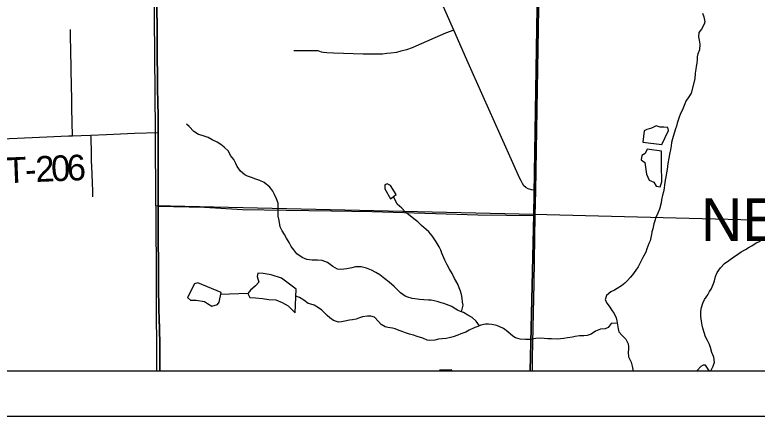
# Model space of a CAD drawing. Extents: x 0 to 34, y -5 to 22.
# Drawn here: x 5.836 to 7.476, y 14 to 14.888 of the extents above; entities that cross this region are included whole.
import ezdxf

# ---------------------------------------------------------------- set-up
doc = ezdxf.new("R2010")
doc.units = 0
for name, color, linetype in [('GM_X_City_Street', 7, 'Continuous'), ('GM_X_Corporation_Text', 7, 'Continuous'), ('GM_X_County_Road', 7, 'Continuous'), ('GM_X_Minor_Lake', 7, 'Continuous'), ('GM_X_Minor_River', 7, 'Continuous'), ('GM_X_Section', 7, 'Continuous'), ('GM_X_Township_Road', 7, 'Continuous'), ('GM_X_Township_Road_Text', 7, 'Continuous'), ('GM_X_US_Route', 7, 'Continuous'), ('SC_Scratch2', 7, 'Continuous'), ('SH_Cut_Line', 7, 'Continuous'), ('SH_Data', 7, 'Continuous')]:
    doc.layers.add(name, color=color, linetype=linetype)

msp = doc.modelspace()

# ---------------------------------------------------------------- linework, layer by layer
at = {"layer": 'GM_X_City_Street'}
for points in [[(6.1486, 14.1), (6.9745, 14.1), (6.9822, 14.4457), (6.1471, 14.4654)], [(6.9745, 14.1), (8.0304, 14.1), (8.041, 14.419), (6.9822, 14.4457)]]:
    msp.add_lwpolyline(points, close=True, dxfattribs=at)
at = {"layer": 'GM_X_County_Road'}
for points in [[(6.987, 14.4985), (6.9943, 14.9477), (7.0004, 15.2464)], [(6.987, 14.4985), (6.9828, 14.4997), (6.9775, 14.5009), (6.9703, 14.5028), (6.9652, 14.5054), (6.9603, 14.5095), (6.9573, 14.5146), (6.9542, 14.5205), (6.9516, 14.5258), (6.9082, 14.623), (6.8707, 14.7073), (6.8348, 14.7884), (6.8057, 14.8538), (6.7632, 14.9507)], [(6.9794, 14.1), (6.9799, 14.1287), (6.9832, 14.2943), (6.9858, 14.4439), (6.987, 14.4985)]]:
    msp.add_lwpolyline(points, dxfattribs=at)
at = {"layer": 'GM_X_Minor_Lake'}
msp.add_line((6.8012, 14.1), (6.8003, 14.1023), dxfattribs=at)
for points in [[(7.2658, 14.6009), (7.2803, 14.6314), (7.2787, 14.6386), (7.2696, 14.6389), (7.2617, 14.6389), (7.2529, 14.6418), (7.2427, 14.6368), (7.2325, 14.634), (7.2261, 14.6313), (7.2233, 14.6058)], [(7.2233, 14.6058), (7.2658, 14.6009)], [(7.2329, 14.5907), (7.2288, 14.5812), (7.2216, 14.5766), (7.2194, 14.5671), (7.2278, 14.5607), (7.2315, 14.5349), (7.2373, 14.522), (7.2476, 14.5175), (7.2526, 14.5085), (7.2621, 14.507), (7.2657, 14.5181), (7.2647, 14.5553), (7.2648, 14.5857)], [(7.2648, 14.5857), (7.2329, 14.5907)], [(6.6783, 14.4902), (6.6656, 14.5102), (6.6584, 14.514), (6.6531, 14.5113), (6.6535, 14.5029), (6.6659, 14.4806)], [(6.6659, 14.4806), (6.6783, 14.4902)], [(6.4572, 14.2805), (6.4247, 14.3053), (6.4019, 14.3127), (6.3841, 14.3152), (6.3727, 14.3162), (6.3709, 14.3086), (6.3751, 14.2965), (6.3676, 14.2881), (6.3567, 14.2789), (6.3503, 14.2716), (6.355, 14.2625), (6.3671, 14.2615), (6.3827, 14.2605), (6.3967, 14.2583), (6.4123, 14.2573), (6.4263, 14.2514), (6.4393, 14.2443), (6.455, 14.2284)], [(6.2398, 14.2946), (6.2326, 14.293), (6.2169, 14.2621), (6.2234, 14.2568), (6.2363, 14.2569), (6.2549, 14.2537), (6.2614, 14.2488), (6.2706, 14.2432), (6.2834, 14.2471), (6.2868, 14.2524), (6.2912, 14.2734)], [(6.2912, 14.2734), (6.2398, 14.2946)], [(6.455, 14.2284), (6.4572, 14.2805)], [(7.3707, 14.1), (7.3701, 14.1006), (7.3647, 14.1082), (7.362, 14.1131), (7.3567, 14.1127), (7.3518, 14.1099), (7.3428, 14.1)], [(6.8003, 14.1023), (6.7742, 14.1017), (6.7746, 14.1)]]:
    msp.add_lwpolyline(points, dxfattribs=at)
at = {"layer": 'GM_X_Minor_River'}
for points in [[(7.3552, 14.8912), (7.3579, 14.8833), (7.3603, 14.8723)], [(7.3603, 14.8723), (7.3592, 14.8666), (7.3532, 14.8559), (7.3469, 14.8486), (7.3466, 14.8391), (7.3478, 14.8319), (7.3494, 14.8228), (7.3484, 14.8102), (7.345, 14.8015), (7.3436, 14.795), (7.3433, 14.7893), (7.3426, 14.7809), (7.3411, 14.7733), (7.3404, 14.7676), (7.339, 14.7585), (7.3384, 14.7459), (7.3304, 14.7143)], [(7.3304, 14.7143), (7.3248, 14.7063), (7.3188, 14.6967), (7.3162, 14.691), (7.3117, 14.6799), (7.3058, 14.6673), (7.3036, 14.6609), (7.2995, 14.6479), (7.2977, 14.6414), (7.2954, 14.6357), (7.2929, 14.6258), (7.2892, 14.6136), (7.287, 14.6053), (7.2859, 14.598), (7.2845, 14.5893), (7.283, 14.5832), (7.2808, 14.5706), (7.2787, 14.5585), (7.2776, 14.552), (7.2769, 14.5455), (7.2758, 14.5383), (7.2744, 14.5284), (7.2729, 14.5216), (7.2711, 14.5113), (7.2704, 14.5041), (7.269, 14.4961), (7.2671, 14.4885), (7.265, 14.4782), (7.2639, 14.4721), (7.2606, 14.458), (7.2569, 14.4492), (7.2524, 14.4397), (7.2498, 14.4317), (7.248, 14.4252), (7.2458, 14.4146), (7.2436, 14.4073), (7.2429, 14.4016), (7.241, 14.3948), (7.2396, 14.3879), (7.237, 14.3815), (7.2325, 14.37), (7.2299, 14.3624), (7.2236, 14.3506), (7.2191, 14.3418), (7.2132, 14.33), (7.2083, 14.3227), (7.2008, 14.3124), (7.1955, 14.3063), (7.1899, 14.3001), (7.1835, 14.294), (7.176, 14.2879), (7.1666, 14.2825), (7.1605, 14.2786), (7.1526, 14.2747), (7.1432, 14.2671), (7.1399, 14.2575), (7.1449, 14.2488), (7.1506, 14.2409), (7.1556, 14.233), (7.1598, 14.2269), (7.1645, 14.2171), (7.1657, 14.211), (7.1673, 14.2019), (7.1689, 14.1932), (7.1704, 14.1864), (7.1777, 14.1785), (7.1857, 14.1702), (7.1908, 14.16), (7.1916, 14.1543), (7.1916, 14.1482), (7.1913, 14.1414), (7.1918, 14.1315), (7.1976, 14.1194), (7.1999, 14.1103), (7.2011, 14.1035), (7.2013, 14.1)], [(6.8625, 14.2), (6.8551, 14.2099), (6.8463, 14.2182), (6.8368, 14.2234), (6.8269, 14.229), (6.8201, 14.2316), (6.814, 14.2346), (6.8067, 14.2387), (6.801, 14.2428), (6.7839, 14.2495), (6.7778, 14.251), (6.7687, 14.2539), (6.7619, 14.2554), (6.7554, 14.2565), (6.7497, 14.2568), (6.7395, 14.2575), (6.73, 14.2582), (6.7194, 14.2592), (6.7137, 14.2603), (6.7042, 14.2629), (6.6981, 14.2651), (6.6881, 14.273), (6.6813, 14.2794), (6.6736, 14.2866), (6.6625, 14.2963), (6.6534, 14.3039), (6.6423, 14.3125), (6.6335, 14.3177), (6.6236, 14.323), (6.6126, 14.3274), (6.6008, 14.3304), (6.5883, 14.3299), (6.5804, 14.3279), (6.5694, 14.3259), (6.5629, 14.3251), (6.5546, 14.3247), (6.5485, 14.3254), (6.5383, 14.331), (6.5268, 14.34), (6.515, 14.3444), (6.5044, 14.3451), (6.4923, 14.345), (6.4812, 14.3464), (6.4702, 14.3509), (6.4591, 14.3592), (6.4522, 14.3675), (6.4461, 14.3754), (6.4415, 14.3837), (6.4361, 14.3935), (6.4315, 14.4018), (6.4265, 14.4102), (6.4222, 14.4189), (6.4195, 14.4325), (6.4178, 14.442), (6.4174, 14.4507), (6.4173, 14.4568), (6.4177, 14.4648), (6.4172, 14.4712), (6.4141, 14.4803), (6.4095, 14.4905), (6.4056, 14.4974), (6.3991, 14.5064), (6.3869, 14.5169), (6.377, 14.521), (6.3682, 14.5244), (6.3587, 14.5277), (6.35, 14.5311), (6.3439, 14.5337), (6.3339, 14.5419), (6.3267, 14.5521), (6.3239, 14.5589), (6.3193, 14.5673), (6.312, 14.5763), (6.3074, 14.5858), (6.2982, 14.5952), (6.291, 14.6008), (6.2826, 14.6057), (6.2719, 14.6113), (6.2628, 14.6162), (6.2563, 14.6188), (6.2498, 14.6206), (6.2415, 14.6232), (6.2312, 14.6299), (6.2209, 14.6409), (6.2147, 14.6454)], [(6.8226, 14.2306), (6.8264, 14.2457), (6.8252, 14.2522), (6.824, 14.2609), (6.8228, 14.2689), (6.8204, 14.2764), (6.8177, 14.2836), (6.8146, 14.2916), (6.8069, 14.3048), (6.8023, 14.3158), (6.7958, 14.3248), (6.7907, 14.3347), (6.7857, 14.3453), (6.7795, 14.3604), (6.7772, 14.3668), (6.773, 14.3748), (6.7668, 14.3858), (6.758, 14.3986), (6.7507, 14.4076), (6.7449, 14.4125), (6.7346, 14.4219), (6.7262, 14.4298), (6.7201, 14.434), (6.706, 14.4452), (6.6991, 14.4513), (6.6911, 14.4599), (6.6804, 14.469), (6.6721, 14.4855)], [(7.3736, 14.1), (7.3791, 14.1103), (7.382, 14.1191), (7.3804, 14.1305), (7.3757, 14.141), (7.373, 14.1517), (7.3706, 14.1585), (7.366, 14.1672), (7.3621, 14.1755), (7.3562, 14.1944), (7.3543, 14.2016), (7.353, 14.2103), (7.3514, 14.2206), (7.3513, 14.232), (7.3528, 14.2403), (7.3561, 14.2499), (7.3594, 14.2579), (7.3673, 14.2682), (7.3706, 14.2755), (7.3747, 14.2812), (7.3792, 14.2915), (7.3818, 14.2992), (7.3843, 14.3087), (7.3877, 14.3178), (7.3952, 14.3278), (7.4042, 14.3374), (7.4132, 14.3443), (7.4242, 14.352), (7.4302, 14.3563), (7.4407, 14.3632), (7.4502, 14.3683), (7.4585, 14.3737), (7.4645, 14.3768), (7.4736, 14.383), (7.4834, 14.3869)], [(6.3503, 14.2716), (6.2903, 14.2693)], [(7.1666, 14.2059), (7.1536, 14.2052), (7.1465, 14.1964), (7.14, 14.1933), (7.1298, 14.1921), (7.1189, 14.1878), (7.1094, 14.1817), (7.1004, 14.1786), (7.0928, 14.1777), (7.0837, 14.1773), (7.0742, 14.1761), (7.0682, 14.1749), (7.0572, 14.1729), (7.0485, 14.1717), (7.0416, 14.1708), (7.0348, 14.1704), (7.0216, 14.1707), (7.0132, 14.171), (7.0052, 14.172), (6.9969, 14.1723), (6.987, 14.1719), (6.9742, 14.1699), (6.9643, 14.1694), (6.9522, 14.1704), (6.9423, 14.173), (6.9362, 14.1768), (6.9251, 14.1862), (6.9156, 14.1941), (6.9011, 14.2004), (6.8897, 14.203), (6.8821, 14.2036), (6.8757, 14.2036), (6.8651, 14.2012), (6.8587, 14.1981), (6.8522, 14.1958), (6.8398, 14.19), (6.8322, 14.1861), (6.8213, 14.1818), (6.8148, 14.1791), (6.8039, 14.1756), (6.7956, 14.1733), (6.7887, 14.1721), (6.78, 14.1712), (6.7721, 14.17), (6.7634, 14.1684), (6.7528, 14.1672), (6.7467, 14.1683), (6.7372, 14.1728), (6.7246, 14.1761), (6.7163, 14.179), (6.7075, 14.1816), (6.6991, 14.1846), (6.6919, 14.1872), (6.6851, 14.1898), (6.6759, 14.1931), (6.6702, 14.1946), (6.6596, 14.1964), (6.6539, 14.1979), (6.6455, 14.2024), (6.639, 14.2095), (6.6302, 14.2186), (6.6222, 14.2208), (6.6147, 14.2215), (6.6041, 14.2195), (6.5973, 14.2171), (6.5901, 14.2148), (6.5817, 14.2132), (6.5749, 14.212), (6.5647, 14.21), (6.5571, 14.2088), (6.5507, 14.208), (6.54, 14.2117), (6.5317, 14.2177), (6.5259, 14.2226), (6.5141, 14.2343), (6.5064, 14.2399), (6.4969, 14.2455), (6.4897, 14.2474), (6.484, 14.2492), (6.4744, 14.2567), (6.4649, 14.2623), (6.4565, 14.2651)]]:
    msp.add_lwpolyline(points, dxfattribs=at)
at = {"layer": 'GM_X_Section'}
for points in [[(6.139, 15.4711), (6.9989, 15.4538), (6.9822, 14.4457), (6.1471, 14.4654), (6.1461, 14.6292)], [(8.0646, 15.4287), (8.041, 14.419), (6.9822, 14.4457), (6.9989, 15.4538)]]:
    msp.add_lwpolyline(points, close=True, dxfattribs=at)
at = {"layer": 'GM_X_Township_Road'}
msp.add_line((6.1526, 14.6274), (6.1525, 14.6385), dxfattribs=at)
for points in [[(6.1525, 14.6385), (6.1523, 14.6635), (6.1517, 14.6944), (6.1513, 14.7224), (6.1509, 14.744), (6.1508, 14.7565), (6.1504, 14.7906), (6.1503, 14.8098), (6.1502, 14.859), (6.1488, 14.9428), (6.1486, 14.9707), (6.1469, 15.0732), (6.1462, 15.1478), (6.1454, 15.1975), (6.1445, 15.2627), (6.1441, 15.2967), (6.1441, 15.2993), (6.1441, 15.3023), (6.1441, 15.3068)], [(5.9628, 14.6201), (5.9616, 14.6802), (5.9613, 14.6999), (5.9607, 14.7331), (5.9601, 14.7642), (5.9592, 14.8139), (5.9587, 14.8343), (5.9586, 14.8374), (5.9586, 14.8418), (5.9586, 14.8469), (5.9588, 14.8554)], [(6.8057, 14.8538), (6.7876, 14.8467), (6.722, 14.818), (6.7134, 14.8145), (6.701, 14.8104), (6.6885, 14.807), (6.6788, 14.8045), (6.6667, 14.8027), (6.6574, 14.8017), (6.6478, 14.8009), (6.6358, 14.8005), (6.605, 14.8008), (6.5396, 14.8029), (6.5251, 14.8035), (6.518, 14.8041), (6.5131, 14.8053), (6.5062, 14.8078), (6.4518, 14.8076)], [(5.807, 14.6136), (5.8237, 14.6143), (5.8737, 14.6163), (5.9541, 14.6198), (5.9628, 14.6201)], [(5.9628, 14.6201), (5.9821, 14.6206), (6.0037, 14.6216)], [(6.0037, 14.6216), (6.038, 14.6232), (6.1, 14.6257), (6.1526, 14.6274)], [(6.0081, 14.4851), (6.0079, 14.4898), (6.0076, 14.4961), (6.007, 14.5176), (6.0063, 14.5331), (6.0055, 14.554), (6.0053, 14.5628), (6.005, 14.5737), (6.0048, 14.5888), (6.0041, 14.609), (6.0039, 14.6165), (6.0037, 14.6216)], [(6.1525, 14.4643), (6.1524, 14.4754), (6.1524, 14.4866), (6.1525, 14.5146), (6.1527, 14.5472), (6.1529, 14.5793), (6.1527, 14.6011), (6.1527, 14.6201), (6.1526, 14.6274)], [(6.1562, 14.1), (6.1562, 14.1018), (6.1561, 14.1297), (6.1559, 14.1576), (6.1551, 14.1934), (6.1548, 14.2147), (6.1543, 14.2353), (6.154, 14.2464), (6.1535, 14.2741), (6.1533, 14.3001), (6.1535, 14.3242), (6.1534, 14.3373), (6.1532, 14.3488), (6.153, 14.3563), (6.1527, 14.3684), (6.1523, 14.4114), (6.1523, 14.4247), (6.1522, 14.4522), (6.1525, 14.4643)], [(6.1525, 14.4643), (6.2547, 14.462), (6.3383, 14.4571), (6.4351, 14.4557), (6.5353, 14.4543), (6.6246, 14.4526), (6.7649, 14.4482), (6.8585, 14.4455), (6.9858, 14.4439)]]:
    msp.add_lwpolyline(points, dxfattribs=at)
at = {"layer": 'GM_X_US_Route'}
for points in [[(2.1, 14.1), (6.156, 14.1), (6.156, 14.1024), (6.1559, 14.1302), (6.1557, 14.1582), (6.1549, 14.194), (6.1545, 14.2153), (6.154, 14.2358), (6.1538, 14.2469), (6.1533, 14.2747), (6.1531, 14.3007), (6.1533, 14.3247), (6.1532, 14.3379), (6.153, 14.3494), (6.1528, 14.3569), (6.1525, 14.369), (6.1521, 14.4119), (6.1521, 14.4253), (6.152, 14.4527), (6.1522, 14.4648), (6.1521, 14.476), (6.1522, 14.4871), (6.1523, 14.5152), (6.1525, 14.5478), (6.1526, 14.5799), (6.1525, 14.6016), (6.1525, 14.6207), (6.1524, 14.6279), (6.1522, 14.6391), (6.1521, 14.6641), (6.1515, 14.695), (6.1511, 14.7229), (6.1507, 14.7446), (6.1506, 14.757), (6.1502, 14.7911), (6.1501, 14.8104), (6.1499, 14.8595), (6.1486, 14.9434)], [(6.1486, 14.9434), (6.1499, 14.8595), (6.1501, 14.8104), (6.1502, 14.7911), (6.1506, 14.757), (6.1507, 14.7446), (6.1511, 14.7229), (6.1515, 14.695), (6.1521, 14.6641), (6.1522, 14.6391), (6.1524, 14.6279), (6.1525, 14.6207), (6.1525, 14.6016), (6.1526, 14.5799), (6.1525, 14.5478), (6.1523, 14.5152), (6.1522, 14.4871), (6.1521, 14.476), (6.1522, 14.4648), (6.152, 14.4527), (6.1521, 14.4253), (6.1521, 14.4119), (6.1525, 14.369), (6.1528, 14.3569), (6.153, 14.3494), (6.1532, 14.3379), (6.1533, 14.3247), (6.1531, 14.3007), (6.1533, 14.2747), (6.1538, 14.2469), (6.154, 14.2358), (6.1545, 14.2153), (6.1549, 14.194), (6.1557, 14.1582), (6.1559, 14.1302), (6.156, 14.1024), (6.156, 14.1), (8.9, 14.1)]]:
    msp.add_lwpolyline(points, dxfattribs=at)
at = {"layer": 'SC_Scratch2'}
msp.add_lwpolyline([(6.1486, 14.9434), (6.1499, 14.8595), (6.1501, 14.8104), (6.1502, 14.7911), (6.1506, 14.757), (6.1507, 14.7446), (6.1511, 14.7229), (6.1515, 14.695), (6.1521, 14.6641), (6.1522, 14.6391), (6.1524, 14.6279), (6.1525, 14.6207), (6.1525, 14.6016), (6.1526, 14.5799), (6.1525, 14.5478), (6.1523, 14.5152), (6.1522, 14.4871), (6.1521, 14.476), (6.1522, 14.4648), (6.152, 14.4527), (6.1521, 14.4253), (6.1521, 14.4119), (6.1525, 14.369), (6.1528, 14.3569), (6.153, 14.3494), (6.1532, 14.3379), (6.1533, 14.3247), (6.1531, 14.3007), (6.1533, 14.2747), (6.1538, 14.2469), (6.154, 14.2358), (6.1545, 14.2153), (6.1549, 14.194), (6.1557, 14.1582), (6.1559, 14.1302), (6.156, 14.1024), (6.156, 14.1), (8.9, 14.1)], dxfattribs=at)
at = {"layer": 'SH_Cut_Line'}
for points in [[(2.1, 14.1), (6.156, 14.1), (6.156, 14.1024), (6.1559, 14.1302), (6.1557, 14.1582), (6.1549, 14.194), (6.1545, 14.2153), (6.154, 14.2358), (6.1538, 14.2469), (6.1533, 14.2747), (6.1531, 14.3007), (6.1533, 14.3247), (6.1532, 14.3379), (6.153, 14.3494), (6.1528, 14.3569), (6.1525, 14.369), (6.1521, 14.4119), (6.1521, 14.4253), (6.152, 14.4527), (6.1522, 14.4648), (6.1521, 14.476), (6.1522, 14.4871), (6.1523, 14.5152), (6.1525, 14.5478), (6.1526, 14.5799), (6.1525, 14.6016), (6.1525, 14.6207), (6.1524, 14.6279), (6.1522, 14.6391), (6.1521, 14.6641), (6.1515, 14.695), (6.1511, 14.7229), (6.1507, 14.7446), (6.1506, 14.757), (6.1502, 14.7911), (6.1501, 14.8104), (6.1499, 14.8595), (6.1486, 14.9434)], [(6.1486, 14.9434), (6.1499, 14.8595), (6.1501, 14.8104), (6.1502, 14.7911), (6.1506, 14.757), (6.1507, 14.7446), (6.1511, 14.7229), (6.1515, 14.695), (6.1521, 14.6641), (6.1522, 14.6391), (6.1524, 14.6279), (6.1525, 14.6207), (6.1525, 14.6016), (6.1526, 14.5799), (6.1525, 14.5478), (6.1523, 14.5152), (6.1522, 14.4871), (6.1521, 14.476), (6.1522, 14.4648), (6.152, 14.4527), (6.1521, 14.4253), (6.1521, 14.4119), (6.1525, 14.369), (6.1528, 14.3569), (6.153, 14.3494), (6.1532, 14.3379), (6.1533, 14.3247), (6.1531, 14.3007), (6.1533, 14.2747), (6.1538, 14.2469), (6.154, 14.2358), (6.1545, 14.2153), (6.1549, 14.194), (6.1557, 14.1582), (6.1559, 14.1302), (6.156, 14.1024), (6.156, 14.1), (8.9, 14.1)]]:
    msp.add_lwpolyline(points, dxfattribs=at)
at = {"layer": 'SH_Data'}
for p, q in [((2.1, 14.1), (8.9, 14.1)), ((2, 14), (9, 14))]:
    msp.add_line(p, q, dxfattribs=at)

# ---------------------------------------------------------------- texts
at = {"layer": 'GM_X_Corporation_Text'}
msp.add_text('NEW FRANKLIN', height=0.094697, rotation=0, dxfattribs=at).set_placement((7.3516, 14.3873))
at = {"layer": 'GM_X_Township_Road_Text'}
for s, rotation, p in [('T', 2.3002, (5.8165, 14.5151)), ('2', 2.2958, (5.882, 14.5178)), ('0', 2.2901, (5.9167, 14.5191)), ('6', 2.2799, (5.9514, 14.5205)), ('-', 2.2992, (5.8589, 14.5168))]:
    msp.add_text(s, height=0.0568, rotation=rotation, dxfattribs=at).set_placement(p)

doc.saveas('drawing.dxf')
